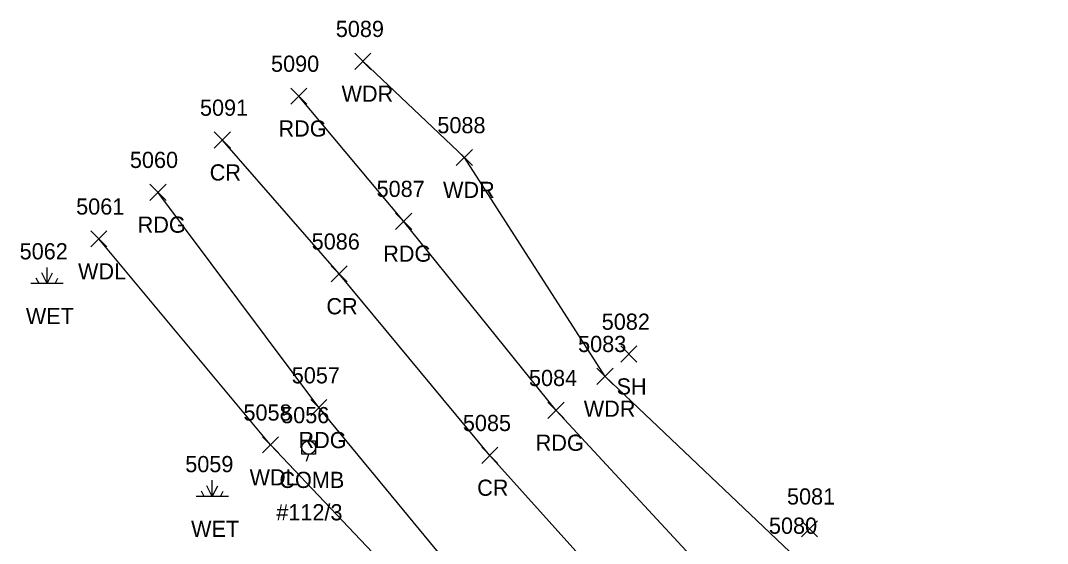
# Model space of a CAD drawing. Extents: x 1653135 to 1655489, y 602711 to 605684.
# Drawn here: x 1653345.8 to 1653472.7, y 605444.4 to 605509 of the extents above; entities that cross this region are included whole.
import ezdxf

# ---------------------------------------------------------------- set-up
doc = ezdxf.new("R2010")
doc.units = 0
for name, color, linetype in [('L_A', 7, 'Continuous'), ('L_I', 7, 'Continuous'), ('L_TIC', 7, 'Continuous'), ('LAWA', 7, 'Continuous'), ('LWET', 7, 'Continuous'), ('P_A', 7, 'Continuous'), ('P_I', 7, 'Continuous'), ('P_TIC', 7, 'Continuous'), ('PEU', 7, 'Continuous'), ('PRC', 7, 'Continuous'), ('U_A', 7, 'Continuous'), ('U_C', 7, 'Continuous'), ('U_I', 7, 'Continuous'), ('UP', 7, 'Continuous')]:
    doc.layers.add(name, color=color, linetype=linetype)

msp = doc.modelspace()

# ---------------------------------------------------------------- linework, layer by layer
at = {"layer": 'L_TIC'}
for points in [[(1653387.1, 605503.01), (1653389.1, 605505.01)], [(1653389.1, 605503.01), (1653387.1, 605505.01)], [(1653387.1, 605503.01), (1653389.1, 605505.01)], [(1653389.1, 605503.01), (1653387.1, 605505.01)], [(1653399.64, 605491.12), (1653401.64, 605493.12)], [(1653401.64, 605491.12), (1653399.64, 605493.12)], [(1653399.64, 605491.12), (1653401.64, 605493.12)], [(1653401.64, 605491.12), (1653399.64, 605493.12)], [(1653354.48, 605481.07), (1653356.48, 605483.07)], [(1653356.48, 605481.07), (1653354.48, 605483.07)], [(1653354.48, 605481.07), (1653356.48, 605483.07)], [(1653356.48, 605481.07), (1653354.48, 605483.07)], [(1653419.95, 605466.84), (1653421.95, 605468.84)], [(1653421.95, 605466.84), (1653419.95, 605468.84)], [(1653419.95, 605466.84), (1653421.95, 605468.84)], [(1653421.95, 605466.84), (1653419.95, 605468.84)], [(1653417.02, 605464.09), (1653419.02, 605466.09)], [(1653419.02, 605464.09), (1653417.02, 605466.09)], [(1653417.02, 605464.09), (1653419.02, 605466.09)], [(1653419.02, 605464.09), (1653417.02, 605466.09)], [(1653375.68, 605455.62), (1653377.68, 605457.62)], [(1653377.68, 605455.62), (1653375.68, 605457.62)], [(1653375.68, 605455.62), (1653377.68, 605457.62)], [(1653377.68, 605455.62), (1653375.68, 605457.62)], [(1653442.28, 605445.25), (1653444.28, 605447.25)], [(1653444.28, 605445.25), (1653442.28, 605447.25)], [(1653442.28, 605445.25), (1653444.28, 605447.25)], [(1653444.28, 605445.25), (1653442.28, 605447.25)]]:
    msp.add_lwpolyline(points, dxfattribs=at)
at = {"layer": 'LAWA'}
for points in [[(1653685.62, 605322.04), (1653670.88, 605332.32), (1653661.72, 605337.52), (1653630.34, 605321.68), (1653616.8, 605320.72), (1653598.43, 605325.95), (1653564.06, 605344.01), (1653534.85, 605363.01), (1653505.82, 605383.05), (1653484.9, 605402.84), (1653463.33, 605422.4), (1653441.69, 605442.64), (1653418.02, 605465.09), (1653400.64, 605492.12), (1653388.1, 605504.01)], [(1653432.37, 605393.1), (1653420.63, 605411.55), (1653397.46, 605434.71), (1653376.68, 605456.62), (1653355.48, 605482.07)]]:
    msp.add_lwpolyline(points, dxfattribs=at)
at = {"layer": 'LWET'}
for p, q in [((1653349.08, 605476.54), (1653348.41, 605477.87)), ((1653349.08, 605476.54), (1653349.08, 605478.54)), ((1653349.08, 605476.54), (1653349.74, 605477.87)), ((1653348.08, 605476.54), (1653347.74, 605477.21)), ((1653350.08, 605476.54), (1653350.41, 605477.21)), ((1653351.08, 605476.54), (1653347.08, 605476.54)), ((1653369.49, 605450.25), (1653368.83, 605451.58)), ((1653369.49, 605450.25), (1653369.49, 605452.25)), ((1653369.49, 605450.25), (1653370.16, 605451.58)), ((1653371.49, 605450.25), (1653367.49, 605450.25)), ((1653368.49, 605450.25), (1653368.16, 605450.92)), ((1653370.49, 605450.25), (1653370.83, 605450.92))]:
    msp.add_line(p, q, dxfattribs=at)
at = {"layer": 'P_TIC'}
for points in [[(1653379.18, 605498.71), (1653381.18, 605500.71)], [(1653381.18, 605498.71), (1653379.18, 605500.71)], [(1653379.18, 605498.71), (1653381.18, 605500.71)], [(1653381.18, 605498.71), (1653379.18, 605500.71)], [(1653369.74, 605493.28), (1653371.74, 605495.28)], [(1653371.74, 605493.28), (1653369.74, 605495.28)], [(1653369.74, 605493.28), (1653371.74, 605495.28)], [(1653371.74, 605493.28), (1653369.74, 605495.28)], [(1653361.78, 605486.83), (1653363.78, 605488.83)], [(1653363.78, 605486.83), (1653361.78, 605488.83)], [(1653361.78, 605486.83), (1653363.78, 605488.83)], [(1653363.78, 605486.83), (1653361.78, 605488.83)], [(1653392.13, 605483.25), (1653394.13, 605485.25)], [(1653394.13, 605483.25), (1653392.13, 605485.25)], [(1653392.13, 605483.25), (1653394.13, 605485.25)], [(1653394.13, 605483.25), (1653392.13, 605485.25)], [(1653384.16, 605476.75), (1653386.16, 605478.75)], [(1653386.16, 605476.75), (1653384.16, 605478.75)], [(1653384.16, 605476.75), (1653386.16, 605478.75)], [(1653386.16, 605476.75), (1653384.16, 605478.75)], [(1653381.65, 605460.22), (1653383.65, 605462.22)], [(1653383.65, 605460.22), (1653381.65, 605462.22)], [(1653381.65, 605460.22), (1653383.65, 605462.22)], [(1653383.65, 605460.22), (1653381.65, 605462.22)], [(1653410.96, 605459.89), (1653412.96, 605461.89)], [(1653412.96, 605459.89), (1653410.96, 605461.89)], [(1653410.96, 605459.89), (1653412.96, 605461.89)], [(1653412.96, 605459.89), (1653410.96, 605461.89)], [(1653402.79, 605454.33), (1653404.79, 605456.33)], [(1653404.79, 605454.33), (1653402.79, 605456.33)], [(1653402.79, 605454.33), (1653404.79, 605456.33)], [(1653404.79, 605454.33), (1653402.79, 605456.33)]]:
    msp.add_lwpolyline(points, dxfattribs=at)
at = {"layer": 'PEU'}
for points in [[(1653653.23, 605280.28), (1653630.46, 605291.02), (1653590.02, 605315.2), (1653557.58, 605338.73), (1653531.08, 605359.13), (1653501.21, 605379.34), (1653479.55, 605396.21), (1653456.3, 605416.21), (1653435.84, 605435.12), (1653411.96, 605460.89), (1653393.13, 605484.25), (1653380.18, 605499.71)], [(1653633.95, 605261.38), (1653608.2, 605278.63), (1653571.73, 605302.8), (1653553.93, 605315.8), (1653535.54, 605328.1), (1653516.91, 605342.14), (1653491.81, 605360.18), (1653469.24, 605376.85), (1653454, 605388.62), (1653441.44, 605399.97), (1653424.23, 605415.49), (1653402.67, 605436.97), (1653382.65, 605461.22), (1653362.78, 605487.83)]]:
    msp.add_lwpolyline(points, dxfattribs=at)
at = {"layer": 'PRC'}
msp.add_lwpolyline([(1653641.51, 605268.82), (1653619.74, 605284.48), (1653584.5, 605306.53), (1653550.68, 605330.05), (1653524.48, 605350.56), (1653495.62, 605372.52), (1653471.48, 605389.99), (1653448.45, 605410.05), (1653429.44, 605426.79), (1653403.79, 605455.33), (1653385.16, 605477.75), (1653370.74, 605494.28)], dxfattribs=at)
at = {"layer": 'UP'}
for p, q in [((1653381.65, 605457.97), (1653381.4, 605457.13)), ((1653380.56, 605455.47), (1653380.56, 605457.13)), ((1653380.56, 605457.13), (1653382.23, 605457.13)), ((1653381.4, 605456.3), (1653381.4, 605456.3)), ((1653382.23, 605457.13), (1653382.23, 605455.47)), ((1653382.23, 605455.47), (1653380.56, 605455.47)), ((1653381.15, 605454.63), (1653381.4, 605455.47))]:
    msp.add_line(p, q, dxfattribs=at)
msp.add_circle((1653381.4, 605456.3), 0.833, dxfattribs=at)

# ---------------------------------------------------------------- texts
at = {"layer": 'L_A'}
for s, p in [('WDR', (1653385.46, 605499.01)), ('WDR', (1653385.46, 605499.01)), ('WDR', (1653398, 605487.12)), ('WDR', (1653398, 605487.12)), ('WDL', (1653352.9, 605477.07)), ('WDL', (1653352.9, 605477.07)), ('WET', (1653346.46, 605471.54)), ('SH', (1653419.44, 605462.84)), ('SH', (1653419.44, 605462.84)), ('WDR', (1653415.39, 605460.09)), ('WDR', (1653415.39, 605460.09)), ('WDL', (1653374.1, 605451.62)), ('WDL', (1653374.1, 605451.62)), ('WET', (1653366.87, 605445.25))]:
    msp.add_text(s, height=2, dxfattribs=at).set_placement(p)
at = {"layer": 'L_I'}
for s, p in [('5089', (1653384.75, 605507.01)), ('5089', (1653384.75, 605507.01)), ('5088', (1653397.3, 605495.12)), ('5088', (1653397.3, 605495.12)), ('5061', (1653352.67, 605485.07)), ('5061', (1653352.67, 605485.07)), ('5062', (1653345.69, 605479.54)), ('5082', (1653417.61, 605470.84)), ('5082', (1653417.61, 605470.84)), ('5083', (1653414.69, 605468.09)), ('5083', (1653414.69, 605468.09)), ('5058', (1653373.34, 605459.62)), ('5058', (1653373.34, 605459.62)), ('5059', (1653366.15, 605453.25)), ('5081', (1653440.5, 605449.25)), ('5081', (1653440.5, 605449.25)), ('5080', (1653438.27, 605445.64)), ('5080', (1653438.27, 605445.64))]:
    msp.add_text(s, height=2, dxfattribs=at).set_placement(p)
at = {"layer": 'P_A'}
for s, p in [('RDG', (1653377.67, 605494.71)), ('RDG', (1653377.67, 605494.71)), ('CR', (1653369.17, 605489.28)), ('CR', (1653369.17, 605489.28)), ('RDG', (1653360.27, 605482.83)), ('RDG', (1653360.27, 605482.83)), ('RDG', (1653390.61, 605479.25)), ('RDG', (1653390.61, 605479.25)), ('CR', (1653383.59, 605472.75)), ('CR', (1653383.59, 605472.75)), ('RDG', (1653380.14, 605456.22)), ('RDG', (1653380.14, 605456.22)), ('RDG', (1653409.45, 605455.89)), ('RDG', (1653409.45, 605455.89)), ('CR', (1653402.22, 605450.33)), ('CR', (1653402.22, 605450.33))]:
    msp.add_text(s, height=2, dxfattribs=at).set_placement(p)
at = {"layer": 'P_I'}
for s, p in [('5090', (1653376.75, 605502.71)), ('5090', (1653376.75, 605502.71)), ('5091', (1653367.97, 605497.28)), ('5091', (1653367.97, 605497.28)), ('5060', (1653359.31, 605490.83)), ('5060', (1653359.31, 605490.83)), ('5087', (1653389.79, 605487.25)), ('5087', (1653389.79, 605487.25)), ('5086', (1653381.77, 605480.75)), ('5086', (1653381.77, 605480.75)), ('5057', (1653379.31, 605464.22)), ('5057', (1653379.31, 605464.22)), ('5084', (1653408.62, 605463.89)), ('5084', (1653408.62, 605463.89)), ('5085', (1653400.45, 605458.33)), ('5085', (1653400.45, 605458.33))]:
    msp.add_text(s, height=2, dxfattribs=at).set_placement(p)
at = {"layer": 'U_A'}
msp.add_text('COMB', height=2, dxfattribs=at).set_placement((1653377.78, 605451.3))
at = {"layer": 'U_C'}
msp.add_text('#112/3', height=2, dxfattribs=at).set_placement((1653377.4, 605447.3))
at = {"layer": 'U_I'}
msp.add_text('5056', height=2, dxfattribs=at).set_placement((1653378, 605459.3))

doc.saveas('drawing.dxf')
